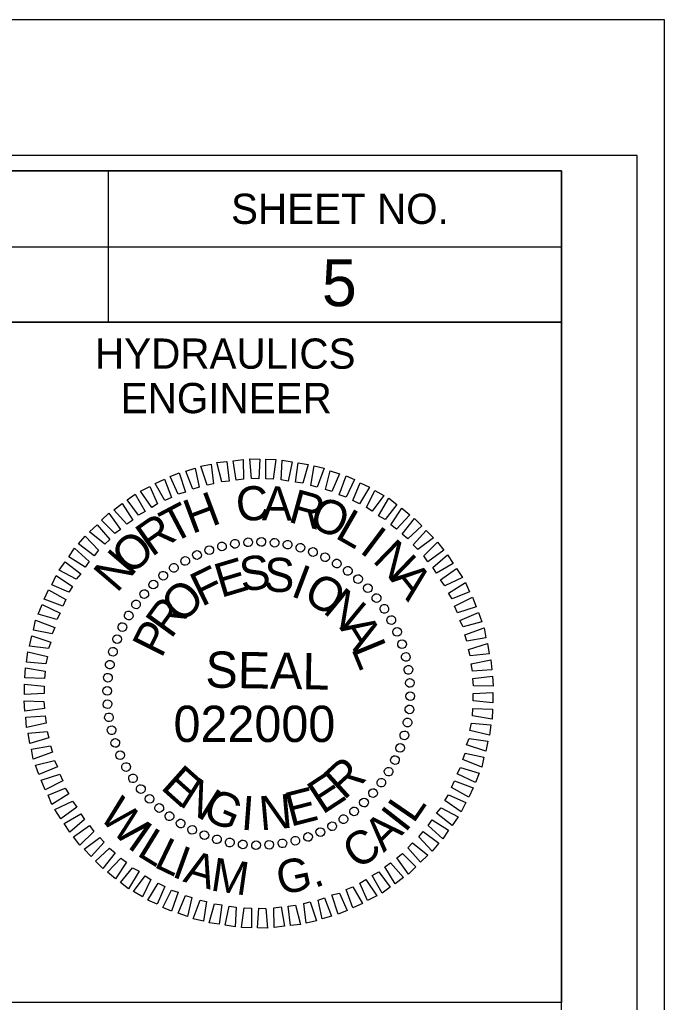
# Model space of a CAD drawing. Extents: x 1019474 to 1021161, y 504129 to 505324.
# Drawn here: x 1021051.6 to 1021158.2, y 505066.8 to 505229.3 of the extents above; entities that cross this region are included whole.
import ezdxf

# ---------------------------------------------------------------- set-up
doc = ezdxf.new("R2010")
doc.units = 0
for name, color, linetype in [('Sheet Cutting Line CELL', 7, 'Continuous'), ('Sheet Data Field CELL', 7, 'Continuous'), ('Sheet Plot Border Inside CELL', 7, 'Continuous'), ('Sheet Plot Border Outside CELL', 7, 'Continuous'), ('Sheet Professional Seal CELL', 7, 'Continuous'), ('Sheet Profile CELL', 7, 'Continuous')]:
    doc.layers.add(name, color=color, linetype=linetype)

msp = doc.modelspace()

# ---------------------------------------------------------------- linework, layer by layer
at = {"layer": 'Sheet Cutting Line CELL'}
msp.add_line((1021158.22, 505229.29), (1019474.22, 505229.29), dxfattribs=at)
at = {"layer": 'Sheet Plot Border Inside CELL'}
msp.add_lwpolyline([(1019487.22, 504151.74), (1021153.72, 504151.74), (1021153.72, 505206.84), (1019487.22, 505206.84)], close=True, dxfattribs=at)
at = {"layer": 'Sheet Plot Border Outside CELL'}
msp.add_lwpolyline([(1019474.22, 504129.29), (1021158.22, 504129.29), (1021158.22, 505229.29), (1019474.22, 505229.29)], close=True, dxfattribs=at)
at = {"layer": 'Sheet Professional Seal CELL'}
for p, q in [((1021087.21, 505142.59), (1021087.21, 505142.59)), ((1021089.36, 505142.89), (1021089.36, 505142.89)), ((1021091.56, 505142.94), (1021091.56, 505142.94)), ((1021093.76, 505142.79), (1021093.76, 505142.79)), ((1021095.91, 505142.44), (1021095.91, 505142.44)), ((1021080.91, 505140.79), (1021080.91, 505140.79)), ((1021082.91, 505141.59), (1021082.91, 505141.59)), ((1021085.01, 505142.19), (1021085.01, 505142.19)), ((1021098.01, 505141.99), (1021098.01, 505141.99)), ((1021100.11, 505141.29), (1021100.11, 505141.29)), ((1021078.96, 505139.79), (1021078.96, 505139.79)), ((1021102.11, 505140.39), (1021102.11, 505140.39)), ((1021104.06, 505139.39), (1021104.06, 505139.39)), ((1021077.06, 505138.64), (1021077.06, 505138.64)), ((1021105.86, 505138.14), (1021105.86, 505138.14)), ((1021073.66, 505135.89), (1021073.66, 505135.89)), ((1021075.31, 505137.39), (1021075.31, 505137.39)), ((1021107.61, 505136.79), (1021107.61, 505136.79)), ((1021072.16, 505134.34), (1021072.16, 505134.34)), ((1021109.16, 505135.29), (1021109.16, 505135.29)), ((1021070.81, 505132.59), (1021070.81, 505132.59)), ((1021110.66, 505133.64), (1021110.66, 505133.64)), ((1021111.91, 505131.89), (1021111.91, 505131.89)), ((1021069.56, 505130.79), (1021069.56, 505130.79)), ((1021113.06, 505129.99), (1021113.06, 505129.99)), ((1021068.56, 505128.84), (1021068.56, 505128.84)), ((1021114.06, 505128.04), (1021114.06, 505128.04)), ((1021067.66, 505126.84), (1021067.66, 505126.84)), ((1021066.96, 505124.74), (1021066.96, 505124.74)), ((1021114.86, 505126.04), (1021114.86, 505126.04)), ((1021115.46, 505123.94), (1021115.46, 505123.94)), ((1021066.51, 505122.64), (1021066.51, 505122.64)), ((1021115.86, 505121.74), (1021115.86, 505121.74)), ((1021066.16, 505120.49), (1021066.16, 505120.49)), ((1021116.16, 505119.59), (1021116.16, 505119.59)), ((1021066.01, 505118.29), (1021066.01, 505118.29)), ((1021091.11, 505117.84), (1021091.11, 505117.84)), ((1021116.21, 505117.39), (1021116.21, 505117.39)), ((1021066.06, 505116.09), (1021066.06, 505116.09)), ((1021116.06, 505115.19), (1021116.06, 505115.19)), ((1021066.36, 505113.94), (1021066.36, 505113.94)), ((1021066.76, 505111.74), (1021066.76, 505111.74)), ((1021115.71, 505113.04), (1021115.71, 505113.04)), ((1021115.26, 505110.94), (1021115.26, 505110.94)), ((1021067.36, 505109.64), (1021067.36, 505109.64)), ((1021114.56, 505108.84), (1021114.56, 505108.84)), ((1021068.16, 505107.64), (1021068.16, 505107.64)), ((1021113.66, 505106.84), (1021113.66, 505106.84)), ((1021069.16, 505105.69), (1021069.16, 505105.69)), ((1021070.31, 505103.79), (1021070.31, 505103.79)), ((1021112.66, 505104.89), (1021112.66, 505104.89)), ((1021071.56, 505102.04), (1021071.56, 505102.04)), ((1021111.41, 505103.09), (1021111.41, 505103.09)), ((1021073.06, 505100.39), (1021073.06, 505100.39)), ((1021110.06, 505101.34), (1021110.06, 505101.34)), ((1021074.61, 505098.89), (1021074.61, 505098.89)), ((1021108.56, 505099.79), (1021108.56, 505099.79)), ((1021076.36, 505097.54), (1021076.36, 505097.54)), ((1021105.16, 505097.04), (1021105.16, 505097.04)), ((1021106.91, 505098.29), (1021106.91, 505098.29)), ((1021078.16, 505096.29), (1021078.16, 505096.29)), ((1021080.11, 505095.29), (1021080.11, 505095.29)), ((1021103.26, 505095.89), (1021103.26, 505095.89)), ((1021082.11, 505094.39), (1021082.11, 505094.39)), ((1021084.21, 505093.69), (1021084.21, 505093.69)), ((1021099.31, 505094.09), (1021099.31, 505094.09)), ((1021101.31, 505094.89), (1021101.31, 505094.89)), ((1021086.31, 505093.24), (1021086.31, 505093.24)), ((1021088.46, 505092.89), (1021088.46, 505092.89)), ((1021090.66, 505092.74), (1021090.66, 505092.74)), ((1021092.86, 505092.79), (1021092.86, 505092.79)), ((1021095.01, 505093.09), (1021095.01, 505093.09)), ((1021097.21, 505093.49), (1021097.21, 505093.49))]:
    msp.add_line(p, q, dxfattribs=at)
for points in [[(1021082.61, 505152.29), (1021081.56, 505155.44), (1021083.26, 505155.79), (1021083.66, 505152.54)], [(1021085.01, 505152.84), (1021084.21, 505156.04), (1021085.86, 505156.19), (1021086.21, 505152.99)], [(1021087.41, 505153.14), (1021086.86, 505156.34), (1021088.56, 505156.54), (1021088.61, 505153.29)], [(1021089.91, 505153.39), (1021089.66, 505156.64), (1021091.31, 505156.59), (1021091.11, 505153.34)], [(1021092.31, 505153.34), (1021092.31, 505156.59), (1021093.96, 505156.54), (1021093.51, 505153.29)], [(1021094.81, 505153.19), (1021095.01, 505156.44), (1021096.66, 505156.14), (1021096.01, 505152.99)], [(1021097.21, 505152.79), (1021097.66, 505155.99), (1021099.31, 505155.74), (1021098.41, 505152.64)], [(1021099.76, 505152.24), (1021100.26, 505155.49), (1021101.96, 505155.09), (1021100.81, 505151.99)], [(1021077.76, 505150.84), (1021076.46, 505153.74), (1021077.96, 505154.34), (1021079.01, 505151.14)], [(1021080.21, 505151.64), (1021079.06, 505154.64), (1021080.61, 505155.09), (1021081.26, 505151.99)], [(1021102.16, 505151.59), (1021102.91, 505154.69), (1021104.46, 505154.19), (1021103.21, 505151.24)], [(1021104.41, 505150.69), (1021105.56, 505153.84), (1021106.96, 505153.24), (1021105.56, 505150.34)], [(1021073.41, 505148.59), (1021071.56, 505151.29), (1021073.11, 505152.09), (1021074.36, 505149.19)], [(1021075.56, 505149.79), (1021073.96, 505152.59), (1021075.51, 505153.29), (1021076.66, 505150.24)], [(1021106.66, 505149.74), (1021107.91, 505152.69), (1021109.46, 505151.99), (1021107.76, 505149.19)], [(1021071.21, 505147.34), (1021069.36, 505149.89), (1021070.66, 505150.84), (1021072.31, 505147.94)], [(1021108.96, 505148.59), (1021110.31, 505151.44), (1021111.81, 505150.59), (1021109.91, 505147.99)], [(1021069.31, 505145.84), (1021067.16, 505148.24), (1021068.51, 505149.29), (1021070.26, 505146.49)], [(1021110.91, 505147.24), (1021112.66, 505150.14), (1021113.96, 505149.09), (1021112.01, 505146.64)], [(1021067.31, 505144.29), (1021065.11, 505146.49), (1021066.31, 505147.69), (1021068.26, 505144.99)], [(1021112.96, 505145.74), (1021114.81, 505148.49), (1021116.11, 505147.39), (1021113.91, 505145.04)], [(1021065.66, 505142.54), (1021063.11, 505144.59), (1021064.36, 505145.74), (1021066.46, 505143.34)], [(1021114.86, 505144.19), (1021116.91, 505146.79), (1021118.11, 505145.59), (1021115.81, 505143.44)], [(1021116.66, 505142.44), (1021118.81, 505144.79), (1021120.01, 505143.59), (1021117.41, 505141.64)], [(1021063.91, 505140.64), (1021061.31, 505142.59), (1021062.41, 505143.89), (1021064.61, 505141.54)], [(1021118.41, 505140.64), (1021120.71, 505142.89), (1021121.76, 505141.54), (1021119.11, 505139.64)], [(1021062.41, 505138.74), (1021059.71, 505140.44), (1021060.66, 505141.89), (1021063.06, 505139.69)], [(1021119.91, 505138.69), (1021122.36, 505140.79), (1021123.31, 505139.34), (1021120.51, 505137.74)], [(1021060.91, 505136.74), (1021058.11, 505138.24), (1021059.11, 505139.64), (1021061.71, 505137.64)], [(1021121.21, 505136.64), (1021123.86, 505138.54), (1021124.81, 505137.04), (1021121.91, 505135.64)], [(1021059.71, 505134.59), (1021056.86, 505135.84), (1021057.61, 505137.39), (1021060.31, 505135.54)], [(1021122.51, 505134.44), (1021125.31, 505136.19), (1021125.96, 505134.64), (1021123.11, 505133.49)], [(1021058.71, 505132.29), (1021055.61, 505133.44), (1021056.36, 505134.99), (1021059.21, 505133.39)], [(1021123.51, 505132.29), (1021126.46, 505133.79), (1021127.11, 505132.19), (1021124.01, 505131.19)], [(1021057.71, 505130.09), (1021054.61, 505130.99), (1021055.26, 505132.54), (1021058.26, 505131.14)], [(1021124.41, 505129.94), (1021127.46, 505131.24), (1021128.01, 505129.69), (1021124.91, 505128.89)], [(1021056.96, 505127.69), (1021053.86, 505128.34), (1021054.21, 505129.99), (1021057.36, 505128.74)], [(1021125.21, 505127.54), (1021128.41, 505128.69), (1021128.71, 505127.04), (1021125.56, 505126.49)], [(1021056.31, 505125.29), (1021053.21, 505125.69), (1021053.56, 505127.39), (1021056.71, 505126.34)], [(1021125.81, 505125.14), (1021128.96, 505126.09), (1021129.26, 505124.39), (1021126.11, 505124.09)], [(1021055.91, 505122.74), (1021052.71, 505123.04), (1021052.91, 505124.74), (1021056.16, 505123.94)], [(1021126.26, 505122.74), (1021129.51, 505123.44), (1021129.66, 505121.74), (1021126.46, 505121.54)], [(1021055.66, 505120.34), (1021052.41, 505120.44), (1021052.51, 505122.09), (1021055.76, 505121.54)], [(1021126.56, 505120.34), (1021129.81, 505120.74), (1021129.91, 505119.04), (1021126.66, 505119.14)], [(1021055.61, 505117.84), (1021052.36, 505117.69), (1021052.36, 505119.39), (1021055.61, 505119.04)], [(1021126.61, 505117.84), (1021129.86, 505117.99), (1021129.86, 505116.29), (1021126.61, 505116.64)], [(1021055.66, 505115.34), (1021052.41, 505114.94), (1021052.31, 505116.64), (1021055.56, 505116.54)], [(1021126.56, 505115.34), (1021129.81, 505115.24), (1021129.71, 505113.59), (1021126.46, 505114.14)], [(1021055.96, 505112.94), (1021052.71, 505112.24), (1021052.56, 505113.94), (1021055.76, 505114.14)], [(1021056.41, 505110.54), (1021053.26, 505109.59), (1021052.96, 505111.29), (1021056.11, 505111.59)], [(1021126.31, 505112.94), (1021129.51, 505112.64), (1021129.31, 505110.94), (1021126.06, 505111.74)], [(1021125.91, 505110.39), (1021129.01, 505109.99), (1021128.66, 505108.29), (1021125.51, 505109.34)], [(1021057.01, 505108.14), (1021053.81, 505106.99), (1021053.51, 505108.64), (1021056.66, 505109.19)], [(1021057.81, 505105.74), (1021054.76, 505104.44), (1021054.21, 505105.99), (1021057.31, 505106.79)], [(1021125.26, 505107.99), (1021128.36, 505107.34), (1021128.01, 505105.69), (1021124.86, 505106.94)], [(1021124.51, 505105.59), (1021127.61, 505104.69), (1021126.96, 505103.14), (1021123.96, 505104.54)], [(1021058.71, 505103.39), (1021055.76, 505101.89), (1021055.11, 505103.49), (1021058.21, 505104.49)], [(1021123.51, 505103.39), (1021126.61, 505102.24), (1021125.86, 505100.69), (1021123.01, 505102.29)], [(1021059.71, 505101.24), (1021056.91, 505099.49), (1021056.26, 505101.04), (1021059.11, 505102.19)], [(1021122.51, 505101.09), (1021125.36, 505099.84), (1021124.61, 505098.29), (1021121.91, 505100.14)], [(1021061.01, 505099.04), (1021058.36, 505097.14), (1021057.41, 505098.64), (1021060.31, 505100.04)], [(1021121.31, 505098.94), (1021124.11, 505097.44), (1021123.11, 505096.04), (1021120.51, 505098.04)], [(1021062.31, 505096.99), (1021059.86, 505094.89), (1021058.91, 505096.34), (1021061.71, 505097.94)], [(1021119.81, 505096.94), (1021122.51, 505095.24), (1021121.56, 505093.79), (1021119.16, 505095.99)], [(1021063.81, 505095.04), (1021061.51, 505092.79), (1021060.46, 505094.14), (1021063.11, 505096.04)], [(1021065.56, 505093.24), (1021063.41, 505090.89), (1021062.21, 505092.09), (1021064.81, 505094.04)], [(1021118.31, 505095.04), (1021120.91, 505093.09), (1021119.81, 505091.79), (1021117.61, 505094.14)], [(1021067.36, 505091.49), (1021065.31, 505088.89), (1021064.11, 505090.09), (1021066.41, 505092.24)], [(1021116.56, 505093.14), (1021119.11, 505091.09), (1021117.86, 505089.94), (1021115.76, 505092.34)], [(1021069.26, 505089.94), (1021067.41, 505087.19), (1021066.11, 505088.29), (1021068.31, 505090.64)], [(1021114.91, 505091.39), (1021117.11, 505089.19), (1021115.91, 505087.99), (1021113.96, 505090.69)], [(1021071.31, 505088.44), (1021069.56, 505085.54), (1021068.26, 505086.59), (1021070.21, 505089.04)], [(1021112.91, 505089.84), (1021115.06, 505087.44), (1021113.71, 505086.39), (1021111.96, 505089.19)], [(1021073.26, 505087.09), (1021071.91, 505084.24), (1021070.41, 505085.09), (1021072.31, 505087.69)], [(1021108.81, 505087.09), (1021110.66, 505084.39), (1021109.11, 505083.59), (1021107.86, 505086.49)], [(1021111.01, 505088.34), (1021112.86, 505085.79), (1021111.56, 505084.84), (1021109.91, 505087.74)], [(1021075.56, 505085.94), (1021074.31, 505082.99), (1021072.76, 505083.69), (1021074.46, 505086.49)], [(1021106.66, 505085.89), (1021108.26, 505083.09), (1021106.71, 505082.39), (1021105.56, 505085.44)], [(1021077.81, 505084.99), (1021076.66, 505081.84), (1021075.26, 505082.44), (1021076.66, 505085.34)], [(1021080.06, 505084.09), (1021079.31, 505080.99), (1021077.76, 505081.49), (1021079.01, 505084.44)], [(1021102.01, 505084.04), (1021103.16, 505081.04), (1021101.61, 505080.59), (1021100.96, 505083.69)], [(1021104.46, 505084.84), (1021105.76, 505081.94), (1021104.26, 505081.34), (1021103.21, 505084.54)], [(1021082.46, 505083.44), (1021081.96, 505080.19), (1021080.26, 505080.59), (1021081.41, 505083.69)], [(1021085.01, 505082.89), (1021084.56, 505079.69), (1021082.91, 505079.94), (1021083.81, 505083.04)], [(1021087.41, 505082.49), (1021087.21, 505079.24), (1021085.56, 505079.54), (1021086.21, 505082.69)], [(1021089.91, 505082.34), (1021089.91, 505079.09), (1021088.26, 505079.14), (1021088.71, 505082.39)], [(1021092.31, 505082.29), (1021092.56, 505079.04), (1021090.91, 505079.09), (1021091.11, 505082.34)], [(1021094.81, 505082.54), (1021095.36, 505079.34), (1021093.66, 505079.14), (1021093.61, 505082.39)], [(1021097.21, 505082.84), (1021098.01, 505079.64), (1021096.36, 505079.49), (1021096.01, 505082.69)], [(1021099.61, 505083.39), (1021100.66, 505080.24), (1021098.96, 505079.89), (1021098.56, 505083.14)]]:
    msp.add_lwpolyline(points, close=True, dxfattribs=at)
for centre, major_axis in [((1021082.94, 505141.55), (-0.234, 0.681)), ((1021085.04, 505142.17), (-0.174, 0.699)), ((1021087.18, 505142.61), (-0.113, 0.711)), ((1021089.36, 505142.86), (-0.05, 0.718)), ((1021091.54, 505142.91), (0.013, 0.72)), ((1021093.73, 505142.78), (0.075, 0.716)), ((1021095.89, 505142.46), (0.137, 0.707)), ((1021098.02, 505141.95), (0.198, 0.692)), ((1021080.9, 505140.75), (-0.293, 0.658)), ((1021100.09, 505141.25), (0.258, 0.672)), ((1021102.1, 505140.38), (0.316, 0.647)), ((1021077.08, 505138.63), (-0.403, 0.597)), ((1021078.95, 505139.77), (-0.349, 0.63)), ((1021104.02, 505139.34), (0.371, 0.617)), ((1021075.32, 505137.33), (-0.453, 0.56)), ((1021105.85, 505138.13), (0.423, 0.582)), ((1021107.56, 505136.77), (0.472, 0.543)), ((1021073.68, 505135.88), (-0.5, 0.518)), ((1021109.15, 505135.26), (0.518, 0.5)), ((1021072.18, 505134.29), (-0.543, 0.472)), ((1021110.6, 505133.62), (0.56, 0.453)), ((1021070.81, 505132.58), (-0.582, 0.423)), ((1021111.9, 505131.86), (0.597, 0.403)), ((1021069.61, 505130.75), (-0.617, 0.371)), ((1021068.56, 505128.83), (-0.647, 0.316)), ((1021113.04, 505130), (0.63, 0.349)), ((1021114.02, 505128.04), (0.658, 0.293)), ((1021067.69, 505126.83), (-0.672, 0.258)), ((1021114.82, 505126), (0.681, 0.234)), ((1021067, 505124.75), (-0.692, 0.198)), ((1021115.44, 505123.9), (0.699, 0.174)), ((1021066.49, 505122.62), (-0.707, 0.137)), ((1021066.16, 505120.46), (-0.716, 0.075)), ((1021115.88, 505121.76), (0.711, 0.113)), ((1021116.12, 505119.59), (0.718, 0.05)), ((1021066.03, 505118.28), (-0.72, 0.013)), ((1021116.18, 505117.4), (0.72, -0.013)), ((1021066.09, 505116.09), (-0.718, -0.05)), ((1021116.05, 505115.22), (0.716, -0.075)), ((1021066.33, 505113.91), (-0.711, -0.113)), ((1021115.72, 505113.05), (0.707, -0.137)), ((1021066.77, 505111.77), (-0.699, -0.174)), ((1021115.21, 505110.92), (0.692, -0.198)), ((1021067.39, 505109.67), (-0.681, -0.234)), ((1021068.19, 505107.64), (-0.658, -0.293)), ((1021114.52, 505108.85), (0.672, -0.258)), ((1021113.65, 505106.84), (0.647, -0.316)), ((1021069.17, 505105.68), (-0.63, -0.349)), ((1021112.6, 505104.92), (0.617, -0.371)), ((1021070.31, 505103.81), (-0.597, -0.403)), ((1021111.4, 505103.1), (0.582, -0.423)), ((1021071.61, 505102.05), (-0.56, -0.453)), ((1021110.03, 505101.38), (0.543, -0.472)), ((1021073.06, 505100.42), (-0.518, -0.5)), ((1021108.53, 505099.8), (0.5, -0.518)), ((1021074.65, 505098.91), (-0.472, -0.543)), ((1021106.89, 505098.35), (0.453, -0.56)), ((1021076.36, 505097.55), (-0.423, -0.582)), ((1021078.19, 505096.34), (-0.371, -0.617)), ((1021105.13, 505097.05), (0.403, -0.597)), ((1021080.11, 505095.3), (-0.316, -0.647)), ((1021082.12, 505094.42), (-0.258, -0.672)), ((1021101.31, 505094.93), (0.293, -0.658)), ((1021103.26, 505095.9), (0.349, -0.63)), ((1021084.19, 505093.73), (-0.198, -0.692)), ((1021086.32, 505093.22), (-0.137, -0.707)), ((1021088.48, 505092.89), (-0.075, -0.716)), ((1021095.03, 505093.07), (0.113, -0.711)), ((1021097.17, 505093.5), (0.174, -0.699)), ((1021099.27, 505094.12), (0.234, -0.681)), ((1021090.67, 505092.76), (-0.013, -0.72)), ((1021092.85, 505092.82), (0.05, -0.718))]:
    msp.add_ellipse(centre, major_axis=major_axis, ratio=0.999708, dxfattribs=at)
at = {"layer": 'Sheet Profile CELL'}
for p, q in [((1021066.22, 505204.24), (1021066.22, 505179.24)), ((1020941.17, 505191.74), (1021141.22, 505191.74))]:
    msp.add_line(p, q, dxfattribs=at)
for points in [[(1021141.22, 505204.29), (1019641.22, 505204.29), (1019641.22, 504154.29), (1021141.22, 504154.29)], [(1020941.17, 505204.29), (1021141.22, 505204.29), (1021141.22, 505179.24), (1020941.17, 505179.24)], [(1021041.22, 505179.24), (1021141.22, 505179.24), (1021141.22, 505066.74), (1021041.22, 505066.74)]]:
    msp.add_lwpolyline(points, close=True, dxfattribs=at)

# ---------------------------------------------------------------- texts
at = {"layer": 'Sheet Data Field CELL'}
msp.add_text('5', height=7.75, dxfattribs=at).set_placement((1021101.57, 505181.91))
at = {"layer": 'Sheet Professional Seal CELL'}
for s, height, rotation, p in [('C', 5.64, 6.2199, (1021087.66, 505146.19)), ('A', 5.64, 359.0203, (1021091.61, 505146.49)), ('H', 5.64, 20.6195, (1021080.06, 505144.19)), ('R', 5.64, 344.6211, (1021095.81, 505146.29)), ('T', 5.64, 27.8198, (1021076.81, 505142.54)), ('O', 5.64, 337.4212, (1021099.16, 505145.54)), ('R', 5.64, 35.0205, (1021073.41, 505140.34)), ('L', 5.64, 330.2209, (1021103.56, 505143.69)), ('O', 5.64, 42.2217, (1021069.96, 505137.24)), ('I', 5.64, 323.0201, (1021107.61, 505141.29)), ('N', 5.64, 315.8189, (1021109.76, 505139.74)), ('N', 5.64, 49.4235, (1021067.66, 505134.34)), ('S', 5.64, 7.2556, (1021088.31, 505134.69)), ('F', 5.64, 25.967, (1021081.66, 505132.14)), ('E', 5.64, 16.6111, (1021084.86, 505133.64)), ('S', 5.64, 357.9004, (1021091.91, 505134.74)), ('I', 5.64, 339.1896, (1021096.21, 505134.04)), ('A', 5.64, 308.6172, (1021112.71, 505136.79)), ('O', 5.64, 44.6812, (1021078.36, 505129.19)), ('O', 5.64, 329.8335, (1021098.21, 505133.34)), ('N', 5.64, 320.4766, (1021101.56, 505131.34)), ('R', 5.64, 54.0397, (1021076.61, 505126.74)), ('P', 5.64, 63.3989, (1021075.01, 505123.54)), ('A', 5.64, 301.7603, (1021104.41, 505128.74)), ('L', 5.64, 292.4008, (1021106.36, 505125.29)), ('SEAL', 5.998, 359, (1021082.26, 505118.84)), ('022000', 5.998, 360, (1021077.02, 505109.83)), ('R', 5.64, 42.4814, (1021105.21, 505100.09)), ('E', 5.64, 318.2769, (1021074.71, 505102.19)), ('E', 5.64, 33.1241, (1021101.66, 505097.74)), ('N', 5.64, 327.634, (1021077.71, 505099.49)), ('G', 5.64, 336.9902, (1021081.51, 505097.24)), ('E', 5.64, 14.4118, (1021096.36, 505095.79)), ('W', 5.5, 313.3349, (1021064.52, 505097.4)), ('I', 5.64, 355.7012, (1021088.06, 505095.34)), ('N', 5.64, 5.0564, (1021091.41, 505095.19)), ('L', 5.5, 55.6002, (1021116.72, 505096.2)), ('I', 5.5, 52.0797, (1021115.35, 505094.67)), ('A', 5.5, 43.8939, (1021111.8, 505091.45)), ('I', 5.5, 324.941, (1021069.17, 505092.47)), ('L', 5.5, 328.4615, (1021070.77, 505091.17)), ('C', 5.5, 35.0212, (1021107.48, 505088.58)), ('L', 5.5, 334.2717, (1021073.58, 505089.25)), ('I', 5.5, 340.0819, (1021076.56, 505087.62)), ('A', 5.5, 343.6024, (1021078.44, 505086.78)), ('M', 5.5, 351.7882, (1021083, 505085.3)), ('G', 5.5, 11.9092, (1021094.68, 505084.49)), ('.', 5.5, 21.8409, (1021100.38, 505085.61))]:
    msp.add_text(s, height=height, rotation=rotation, dxfattribs=at).set_placement(p)
at = {"layer": 'Sheet Profile CELL'}
for s, p in [('SHEET NO.', (1021086.53, 505195.51)), ('HYDRAULICS', (1021064.03, 505171.56)), ('ENGINEER', (1021068.28, 505164.21))]:
    msp.add_text(s, height=5, dxfattribs=at).set_placement(p)

doc.saveas('drawing.dxf')
